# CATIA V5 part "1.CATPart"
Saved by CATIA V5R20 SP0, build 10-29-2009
Part number: Part1
Bounding box of the stored display mesh (mm): x -20 to 25, y -55 to 55, z 0 to 149.99
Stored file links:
  C:\Users\Ehsan Fathi\Desktop\Part1.CATPart
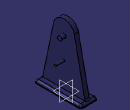
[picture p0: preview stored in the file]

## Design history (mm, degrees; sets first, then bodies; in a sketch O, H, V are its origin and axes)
Body1 (main body)
  Sketch1 on yz-plane, origin (0, 0, 0), H (0, 1, 0), V (0, 0, 1)
    point P1 (-55, 0)
    line L1 (-55, 0) -> (55, 0)
    line L2 (55, 0) -> (55, 2)
    line L3 (50, 7) -> (-50, 7)
    line L4 (-55, 2) -> (-55, 0)
    circle A1 centre (0, 65) radius 2.5
    point P3 (0, 65)
    circle A2 centre (0, 115) radius 5
    point P4 (0, 115)
    arc A3 centre (0, 125) radius 25 from (24.4793, 130.076) to (-24.4793, 130.076) ccw
    point P5 (0, 125)
    arc A4 centre (50, 2) radius 5 from (55, 2) to (50, 7) ccw
    arc A5 centre (-50, 2) radius 5 from (-50, 7) to (-55, 2) ccw
    point P9 (-50, 7)
    line L5 (-50, 7) -> (-24.4793, 130.076)
    point P12 (-50, 7)
    point P13 (-24.4793, 130.076)
    point P14 (24.4793, 130.076)
    point P15 (50, 7)
    line L6 (50, 7) -> (24.4793, 130.076)
    distance P1 V = 55
    distance P1 H = 0
    distance L1 L3 = 7
    distance L2 L4 = 110
    distance P3 V = 0
    distance P3 H = 65
    radius A1 = 2.5
    distance P4 V = 0
    distance P4 H = 115
    radius A2 = 5
    distance P5 H = 125
    radius A3 = 25
    radius A4 = 5
    radius A5 = 5 {= Sketch1.radius(A4)}
    horizontal: L1 H, L3 H
    vertical: L2 V, L4 V
    tangency: A4 L2, A4 L3, A5 L3, A5 L4, L5 A3
    coincidence: P9 P12
    symmetry: P13 P14 V, P12 P15 V, L5 L6 V
  MultiPad1: profile Sketch1, domains (length 20 / length 20; length 5 / length 5; length 15 / length 5; length 25 / length 5)
  Fillet1: radius 5, on edge [face of MultiPad1 from Sketch1.L3 | face of MultiPad1]; edge [face of MultiPad1 | face of MultiPad1 from Sketch1.L3]
  Fillet2: radius 5, on edge [face of MultiPad1 from Sketch1.L6 | face of MultiPad1 from Sketch1.A4]; edge [face of MultiPad1 from Sketch1.A5 | face of MultiPad1 from Sketch1.L5]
